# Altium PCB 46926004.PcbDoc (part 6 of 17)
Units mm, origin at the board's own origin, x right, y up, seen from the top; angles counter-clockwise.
Board outline 250 x 200 mm, 6 copper layers (Top Layer, INT1_GND, INT2_SIG, INT3_SIG, INT4_GND, Bottom Layer), stack 1.71 mm thick; 1450 components, 1293 nets, 5656 pads, 2307 vias.
Unrouted connection lines stored in the file: 2.
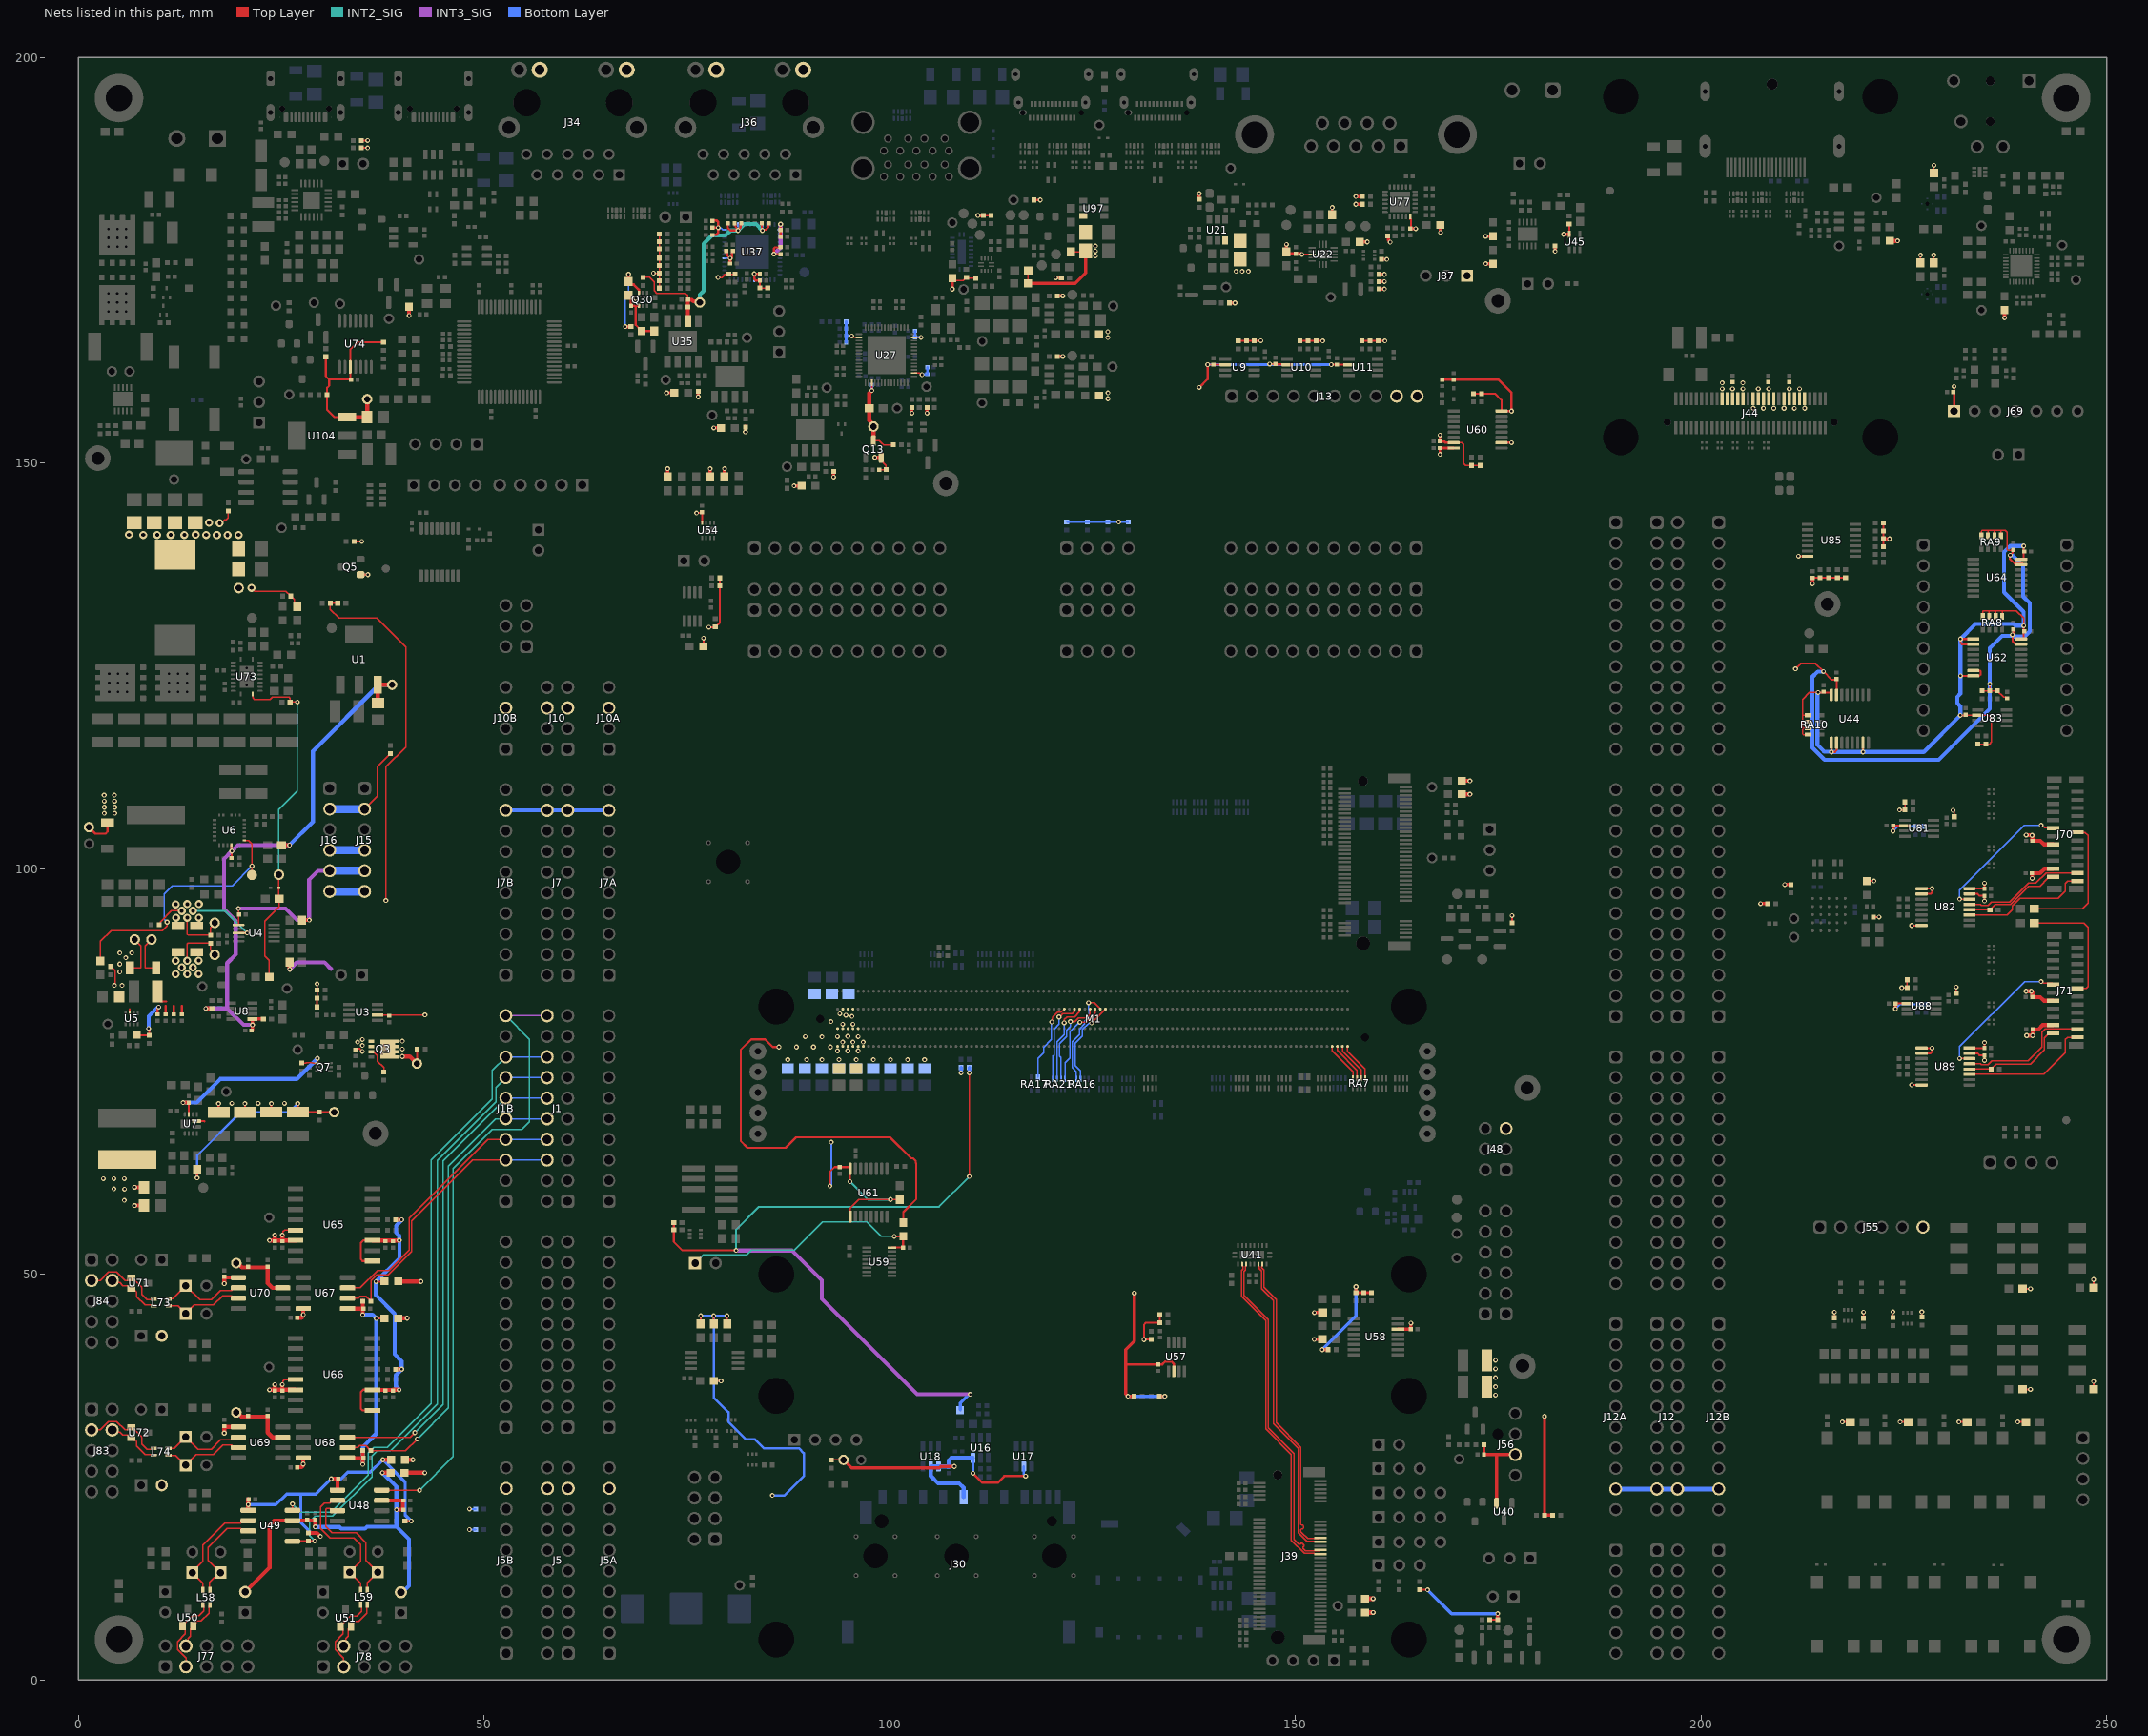
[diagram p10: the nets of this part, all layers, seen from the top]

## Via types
v1: diameter 0.6, hole 0.3, Top Layer to Bottom Layer, tented both sides, 2171 vias
v2: diameter 0.6, hole 0.3, Top Layer to Bottom Layer, 48 vias
v3: diameter 1, hole 0.5, Top Layer to Bottom Layer, tented both sides, 37 vias
v4: diameter 0.5, hole 0.2, Top Layer to Bottom Layer, tented both sides, 34 vias
v5: diameter 0.6, hole 0.3, Top Layer to Bottom Layer, tented bottom, 17 vias

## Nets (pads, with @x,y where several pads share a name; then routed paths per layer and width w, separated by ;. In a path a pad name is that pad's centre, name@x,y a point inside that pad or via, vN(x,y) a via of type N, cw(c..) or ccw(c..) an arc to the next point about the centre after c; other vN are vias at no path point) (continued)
1V8: C8.2 C65.2 C66.2 C69.2 C96.2 C98.1 C207.2 C228.2 C234.2 C239.2 C241.2 C242.2 C245.2 C304.1 C311.2 C312.2 C317.2 C318.2 C342.2 C351.2 C354.2 C359.2 C393.2 C394.2 J5.17 J5.18 J5A.9 J5B.9 J7.17 J7.18 J7A.9 J7B.9 J10.5 J10.6 J10A.3 J10B.3 J12.17 J12.18 J12A.9 J12B.9 J15.6 J16.6 J44.43 J44.45 J44.47 J44.49 J44.51 J48.5 J55.6 J69.1 J87.1 L21.1 L57.1 L60.1 L62.2 L63.1 L72.1 L78.1 Q5.1 Q30.4 R39.2 R61.1 R66.1 R75.1 R76.1 R108.1 R118.1 R140.1 R141.1 R180.2 R182.1 R193.1 R198.1 R221.1 R222.1 R223.1 R230.1 R231.1 R232.1 R233.1 R234.1 R238.1 R240.1 R242.1 R244.1 R246.1 R255.1 R258.1 R260.1 R262.1 R266.1 R268.1 R269.1 R271.1 R284.2 R300.1 R302.1 R340.1 R343.2 R383.2 R384.2 R385.2 R391.2 R392.1 R408.2 R409.2 R410.2 R411.2 R412.2 R413.1 R414.1 R418.2 R426.1 R427.1 R432.2 R442.1 R443.1 R455.1 R456.1 R468.2 R469.2 R470.2 R471.2 R472.2 R475.2 R476.2 R477.1 R478.1 RA8.5 RA8.6 RA8.7 RA8.8 RA10.5 RA10.6 RA10.7 RA10.8 U3.2 U9.2 U10.2 U11.2 U44.1 U44.2 U44.7 U44.16 U45.5 U54.8 U57.2 U60.2 U60.8 U60.16 U61.1 U61.16 U62.1 U62.2 U62.7 U62.8 U62.16 U64.16 U77.18 U81.2 U82.1 U82.2 U82.8 U82.16 U83.2 U85.14 U88.2 U89.1 U89.2 U89.8 U89.16 X19.1 | length 396.5
  Top Layer w0.15: R39.2@6.375,87.775 7.637,87.775 7.725,87.863 7.725,90.489 X19.1@6.941,91.273 ; U3.2@36.87,81.975 v1(42.721,81.975) ; U61.1@95.114,56.814 95.114,58.181 96.172,59.239 100.093,59.239 v1(100.102,59.23) 100.111,59.239 R284.2@101.239,59.239 ; RA10.8@213.175,116.525 212.578,116.525 212.5,116.603 212.5,117.325 ; RA10.7@213.175,117.325 212.5,117.325 ; RA10.6@213.175,118.125 212.5,118.125 ; RA10.5@213.175,118.925 212.5,118.925 ; v1(214.425,121.725) 213.354,121.725 212.5,120.871 212.5,118.925 ; R302.1@227.05,174.675 v1(227.05,175.625) ; R340.1@228.675,174.675 v1(228.675,175.625) ; R300.1@228.7,185.75 v1(228.7,186.7) ; v1(231.175,159.45) 231.175,158.8 231.2,158.775 C342.2@231.2,158.525 ; C351.2@232.625,118.9 U83.2@234.105,118.9 235.425,118.9 235.8,118.525 235.8,115.6 235.55,115.35 R442.1@235.1,115.35 R443.1@234.1,115.35 ; RA8.8@234.712,131.125 234.712,131.722 234.79,131.8 235.512,131.8 ; RA8.7@235.512,131.125 235.512,131.8 ; RA8.6@236.312,131.125 236.312,131.8 ; RA8.5@237.112,131.125 237.112,131.8 ; v1(239.75,129.95) 239.75,130.875 238.825,131.8 237.112,131.8 ; 212.5,117.325 212.5,118.125 ; 212.5,118.125 212.5,118.925 ; 235.512,131.8 236.312,131.8 ; 236.312,131.8 237.112,131.8
  Top Layer w0.25: Q5.1@34.764,136.25 v1(35.689,136.25) ; 68.684,169.389 68.684,167.042 C98.1@69.302,166.425 ; v1@76.2,143.843 C228.2@76.865,143.843 ; R232.1@76.7,43.9 v1(76.7,44.9) ; U54.8@76.87,142.663 C228.2@76.87,143.838 ; L21.1@77.05,127.425 v1(77.05,128.425) ; L63.1@78.295,36.865 v1(79.2,36.865) ; R233.1@78.3,43.9 v1(78.3,44.9) ; R234.1@79.95,43.9 v1(79.95,44.9) ; v1(92.613,60.881) 92.613,62.626 93.2,63.214 C239.2@93.814,63.214 94.991,63.214 U61.16@95.114,63.091 ; v1(95.114,61.429) U61.16@95.114,63.014 U61.16@95.114,63.091 ; U61.16@95.114,63.314 U61.16@95.114,63.091 ; R391.2@117.795,182.432 v1(118.55,182.432) ; v1(139.19,162.133) C65.2@139.885,162.133 ; C65.2@140,162.13 140.002,162.128 141.357,162.128 U9.2@141.36,162.125 ; v1(146.829,162.2) C66.2@147.515,162.2 147.552,162.163 148.942,162.163 U10.2@148.98,162.125 ; v1(154.43,162.133) C69.2@155.125,162.133 ; C69.2@155.24,162.13 155.242,162.128 156.597,162.128 U11.2@156.6,162.125 ; C304.1@164.15,178.9 164.249,178.999 164.249,179.951 164.156,180.044 164.156,180.179 U77.18@164.15,180.185 U77.18@164.15,180.375 ; v1@164.817,178.898 v1(164.82,178.895) ; R193.1@165.33,11.125 v1(166.3,11.125) ; C354.2@167.823,151.85 C354.2@167.826,151.852 ; U60.16@169.498,151.852 U60.16@169.5,151.855 ; R456.1@171.95,158.55 R455.1@172.95,158.55 174.601,158.55 175.4,157.751 U60.8@175.4,156.405 ; R182.1@173.937,7.423 R418.2@174.928,7.423 ; R198.1@176.693,93.35 v1(176.693,94.235) ; v1(181.995,176.111) v1@181.997,176.114 ; R432.2@181.997,176.779 R432.2@182,176.781 ; R343.2@183.725,179.475 183.737,179.462 183.737,178.213 U45.5@183.748,178.202 ; v1(212.004,138.525) U85.14@213.121,138.525 ; C359.2@213.725,135.86 R476.2@214.672,135.86 R469.2@215.75,135.86 R468.2@216.8,135.86 R408.2@217.8,135.86 ; v1(214.425,121.725) U44.16@216.05,121.725 ; U44.1@216.05,115.225 v1(216.05,114.4) 216.511,114.4 216.7,114.589 U44.2@216.7,115.225 ; v1(217.401,31.811) R246.1@218.409,31.811 ; U44.7@219.95,115.225 219.956,115.219 219.956,114.406 v1(219.961,114.4) ; L62.2@220.41,98.485 v1(221.31,98.485) ; R230.1@221.25,94.05 v1(221.925,94.05) ; R475.2@222.484,139.681 R472.2@222.484,142.603 ; C311.2@223.666,105.315 U81.2@225.12,105.315 ; C317.2@223.951,83.39 U88.2@225.404,83.39 ; v1(224.526,31.811) R244.1@225.534,31.811 ; v1@225.964,73.348 U89.8@227.179,73.348 ; v1@225.965,93 U82.8@227.18,93 ; U89.2@227.179,77.248 228.308,77.248 228.454,77.395 v1(228.454,77.898) U89.1@227.179,77.898 ; U82.2@227.18,96.9 228.308,96.9 228.455,97.046 v1(228.455,97.55) U82.1@227.18,97.55 ; J69.1@231.17,156.4 231.2,156.43 C342.2@231.2,158.525 ; v1(231.776,31.811) R242.1@232.784,31.811 ; v1(231.95,118.9) C351.2@232.625,118.9 ; v1@231.997,123.775 U62.8@233.55,123.775 234.304,123.775 234.45,123.921 234.45,124.314 234.339,124.425 U62.7@233.25,124.425 ; U89.16@233.079,77.898 C318.2@234.929,77.898 v1(234.929,78.562) ; U82.16@233.08,97.55 C312.2@234.93,97.55 v1(234.93,98.214) ; U62.2@233.25,127.675 232.121,127.675 231.975,127.821 v1(231.975,128.325) U62.1@233.25,128.325 ; v1(239.026,31.811) R240.1@240.034,31.811 ; R255.1@239.625,35.825 v1(240.6,35.825) ; R258.1@239.625,48.225 v1(240.6,48.225) ; U62.16@239.75,128.325 v1(239.75,129.95) ; U64.16@239.75,138.15 v1(239.75,139.775) ; R260.1@248.375,35.825 v1(248.375,36.8) ; R262.1@248.375,48.375 v1(248.375,49.35)
  Top Layer w0.3: R180.2@67.8,170.7 67.8,170.577 R180.2@67.814,170.563 ; v1(68.67,170.263) 68.124,170.263 C96.2@68.124,169.389 68.684,169.389 Q30.4@69.076,169.389 ; C98.1@69.302,166.425 69.441,166.285 C98.1@69.441,166.26 R61.1@70.95,166.26 ; v1(85.525,22.761) v1@85.539,22.775 ; 129.1,38.977 129.177,38.9 C234.2@133.063,38.9 133.602,38.9 133.952,39.25 134.729,39.25 135.002,38.977 U57.2@135.002,38.065 ; v1(138.15,159.325) 139.19,160.365 v1(139.19,162.133) ; v1(167.826,151.077) 167.826,151.852 U60.16@169.498,151.852 ; C393.2@168.083,160.285 174.995,160.285 176.625,158.655 v1(176.625,156.405) U60.8@175.4,156.405 ; U60.2@175.4,152.505 v1(176.625,152.505)
  Top Layer w0.4: R221.1@72.62,148.31 v1(72.62,149.31) ; R222.1@77.87,148.31 v1(77.87,149.31) ; R223.1@79.62,148.31 v1(79.62,149.31) ; v1(120.47,172.843) R392.1@121.15,172.843 ; R141.1@120.644,170.613 v1(121.324,170.613) ; R140.1@120.654,163.14 v1(121.334,163.14) ; R477.1@130.118,34.978 v1(129.351,34.978) 129.1,35.229 129.1,38.977 129.1,40.742 130.143,41.784 130.143,41.809 130.145,41.811 130.145,47.681 v1(130.147,47.683) ; R478.1@133.241,34.978 v1(133.9,34.978) ; R108.1@138.145,182.536 138.147,182.538 138.147,183.203 v1(138.15,183.206) ; v1(153.298,40.712) R266.1@154.024,40.712 ; v1(157.45,182.85) R384.2@158.25,182.85 ; v1(157.45,181.9) R383.2@158.25,181.9 ; v1(157.461,48.468) R271.1@157.461,47.743 R269.1@158.411,47.743 R268.1@159.359,47.743 ; R118.1@160.299,171.463 160.964,171.463 v1(160.966,171.46) ; R385.2@161.348,177.998 161.352,177.998 161.45,177.9 161.45,177.505 161.67,177.285 v1(161.67,177.231) ; C304.1@164.249,178.898 v1@164.817,178.898 ; v1(173.45,174.575) L78.1@174.375,174.575 ; R418.2@174.928,7.423 v1(174.928,8.187) ; v1@181.997,176.114 R432.2@181.997,176.779 ; v1(183.08,178.205) 183.083,178.202 U45.5@183.748,178.202 ; v1(207.325,95.7) 207.437,95.7 R231.1@208.185,95.7 ; v1(210.312,98.04) R238.1@211.06,98.04 ; v1@213.725,135.115 C359.2@213.725,135.86 ; R470.2@222.484,140.656 v1@223.228,140.656 ; v1(223.661,104.645) 223.664,104.648 C311.2@223.664,105.313 ; v1(223.946,82.72) 223.948,82.723 C317.2@223.948,83.388
  Top Layer w0.5: L72.1@39.456,44.525 39.516,44.585 40.525,44.585 v1(40.535,44.595) ; L57.1@40.225,27.15 v1(41.225,27.15) ; v1(237.4,167.9) L60.1@237.4,168.85
  INT2_SIG w0.25: v1(95.114,61.429) 97.313,59.23 v1(100.102,59.23)
  Bottom Layer w0.15: R413.1@121.8,142.725 R414.1@124.34,142.725 R426.1@126.88,142.725 R427.1@129.42,142.725
  Bottom Layer w0.25: v1(48.2,18.54) R75.1@48.955,18.54 ; v1(48.2,21.08) R76.1@48.955,21.08 ; v1(76.7,44.9) v1(78.3,44.9) v1(79.95,44.9) ; v1(92.613,60.881) 92.792,61.061 v1(92.792,66.29) ; v1(223.661,104.645) 224.241,105.225 R409.2@226.416,105.225 R410.2@227.409,105.225 ; v1(223.946,82.72) 224.525,83.3 R411.2@226.7,83.3 R412.2@227.694,83.3
  Bottom Layer w0.3: v1(78.3,44.9) 78.3,34.825 80.125,33 80.125,31.82 82.283,29.662 83.391,29.662 84.475,28.578 87.377,28.578 87.386,28.57 88.785,28.57 89.4,27.955 89.4,25.141 87.02,22.761 v1(85.525,22.761)
  Bottom Layer w0.4: v1(108.8,74.84) R66.1@108.8,75.5 ; v1(129.351,34.978) v1(133.9,34.978) ; v1(139.19,162.133) v1(154.43,162.133) ; v1(153.298,40.712) 157.461,44.875 v1(157.461,48.468) ; v1(166.3,11.125) 169.239,8.187 v1(174.928,8.187)
  Bottom Layer w0.5: J7B.9@52.68,107.2 J7.18@57.76,107.2 J7.17@60.3,107.2 J7A.9@65.38,107.2 ; v1(214.425,121.725) 214.345,121.645 214.345,115.241 215.167,114.419 216.031,114.419 v1(216.05,114.4) v1(219.961,114.4) 227.45,114.4 v1(231.95,118.9) 231.963,118.913 231.963,120.022 231.575,120.41 231.575,121.192 231.963,121.58 231.963,128.313 v1(231.975,128.325) 233.817,130.167 238.547,130.167 238.763,129.95 v1(239.75,129.95) 239.75,131.675 237.35,134.075 237.35,139.025 238.1,139.775 v1(239.75,139.775)
  Bottom Layer w0.6: J12A.9@189.47,23.54 J12.17@194.55,23.54 J12.18@197.09,23.54 J12B.9@202.17,23.54
  Bottom Layer w1: J16.6@30.977,97.204 J15.6@35.277,97.204
  other v1: 225.959,73.353 5.103,87.277 5.103,88.25 5.825,89.025 5.103,89.608 6.575,89.608 225.96,93.005 231.986,123.786 213.722,135.112 223.231,140.653 128.22,142.725 76.195,143.848 210.227,156.75 211.507,156.74 212.767,156.75 210.862,159.15 212.132,159.15
1V8_CAN_A: C209.2 C210.2 L57.2 R43.1 R50.1 U48.5 U49.5 | length 41.5
  Top Layer w0.15: U48.5@31.919,23.405 U48.5@31.925,23.41 ; R50.1@40.25,19.6 v1(41.025,19.6)
  Top Layer w0.5: U49.5@20.924,20.916 20.925,20.917 v1(20.925,21.625) 20.925,22.304 C210.2@20.924,22.305 ; R43.1@28.351,18.133 29.392,18.133 v1(29.825,17.7) ; v1(31.15,24.8) 31.925,24.8 U48.5@31.925,23.41 ; v1(37.525,27.15) L57.2@38.525,27.15
  Bottom Layer w0.4: v1(20.925,21.625) 24.35,21.625 25.66,22.935 27.414,22.935 ; v1(29.825,17.7) 29.771,17.7 29.338,18.133 28.651,18.133 27.414,19.371 27.414,22.935 ; v1(41.025,19.6) 40.275,20.35 40.275,24.4 v1(37.525,27.15) 35.975,25.6 33.2,25.6 32.4,24.8 v1(31.15,24.8) 29.285,22.935 27.414,22.935
1V8_CAN_B: C251.2 C252.2 L72.2 R67.1 R68.1 U67.1 U68.1 | length 28.7
  Top Layer w0.15: U68.1@33.169,27.38 U68.1@33.189,27.36 ; L72.2@37.69,44.55 L72.2@37.704,44.565
  Top Layer w0.25: v1(36.725,44.55) L72.2@37.69,44.55
  Top Layer w0.5: U67.1@33.173,45.795 33.194,45.775 C251.2@35.05,45.775 ; U68.1@33.189,27.36 C252.2@35.045,27.36 ; v1(35.045,26.58) C252.2@35.045,27.36 ; R68.1@35.045,28.285 C252.2@35.045,27.36 ; v1(35.05,45.025) C251.2@35.05,45.775 ; R67.1@35.05,46.7 C251.2@35.05,45.775
  Bottom Layer w0.5: v1(35.045,26.58) 35.045,28.695 36.725,30.375 v1(36.725,44.55) 36.25,45.025 v1(35.05,45.025)
1V8_ETH2: C99.1 C130.1 C141.2 C142.2 C143.2 C157.2 C161.2 C165.2 C168.2 C171.1 C174.1 C178.1 Q30.3 R62.2 R150.2 R152.2 R154.2 R156.1 R158.2 R162.2 R164.2 R168.2 R173.2 R174.2 R175.2 R180.1 R450.2 U37.13 U37.19 U37.30 U37.41 U37.48 | length 42.2
  Top Layer w0.15: v1(70.876,173.412) R156.1@71.595,173.412 ; R150.2@71.595,171.562 R156.1@71.595,173.412 ; R162.2@71.595,178.237 R164.2@71.595,177.312 R158.2@71.595,176.387 R156.1@71.595,173.412 ; v1(78.825,172.875) 79.293,172.875 79.693,173.275 R154.2@80.15,173.275 80.155,173.28 R152.2@80.92,173.28
  Top Layer w0.2: R175.2@83.988,171.575 84.949,171.575 R174.2@84.958,171.583 ; R175.2@83.988,171.575 C174.1@83.988,172.525
  Top Layer w0.25: C157.2@79.85,176.025 79.975,175.9 79.975,175.571 80.296,175.25 v1(80.325,175.25) 80.325,174.75 80.374,174.701 C171.1@80.385,174.701 ; v1@80.55,175.375 80.55,175.925 C161.2@80.65,176.025 ; C178.1@86.55,175.75 v1(85.725,175.75) 85.725,176.454 85.871,176.6 C168.2@86.55,176.6
  Top Layer w0.3: R180.1@67.814,172.279 68.093,172 68.441,172 69.076,171.366 Q30.3@69.076,170.969 ; C130.1@78.125,178.16 78.65,178.16 78.875,178.385 v1(78.875,179.01) ; C142.2@78.125,179.01 v1(78.875,179.01) ; C143.2@78.125,179.91 78.65,179.91 78.7,179.86 78.875,179.685 v1(78.875,179.01) ; C174.1@83.988,172.525 83.466,172.525 83.3,172.691 v1(83.3,173.35) C165.2@83.988,173.35 ; C99.1@86.55,177.925 v1(86.55,179.44)
  Top Layer w0.4: v1(67.418,166.81) R173.2@68.098,166.81 ; R180.1@67.8,172.4 v1(67.8,173.288) ; C171.1@80.325,174.585 v1(80.325,175.25)
  INT3_SIG w0.5: v1(85.725,175.75) 86.55,176.575 v1(86.55,179.44)
  Bottom Layer w0.15: v1(67.418,166.81) 67.418,170.32 67.798,170.699 67.798,173.151 v1@67.814,173.167
  Bottom Layer w0.2: v1(78.875,179.01) 78.952,178.933 79.276,178.933 79.459,178.75 U37.48@79.65,178.75 ; U37.41@79.65,175.25 v1(80.325,175.25) ; U37.30@83.3,172.6 v1(83.3,173.35) ; v1(85.725,175.75) U37.19@86.45,175.75 ; U37.13@86.45,178.75 86.482,178.75 86.5,178.768 86.5,179.39 v1(86.55,179.44)
2V5_ETH2: C153.2 C163.2 C166.2 C169.2 C172.1 C175.1 R121.2 R169.2 U35.6 U37.3 U37.9 X56.1 | length 35.4
  Top Layer w0.15: R121.2@69.576,172.89 70.395,172.89 70.95,172.335 70.95,171.282 71.295,170.937 74.819,170.937 75.098,170.658 75.098,170.173 C153.2@75.125,170.146
  Top Layer w0.25: C166.2@80.05,179.575 80.05,178.975 80.35,178.675 v1(81.3,178.675) ; C163.2@80.875,179.475 80.91,179.44 80.975,179.44 80.975,179.125 81.233,178.867 81.233,178.742 v1(81.3,178.675) ; C172.1@81.7,179.475 81.649,179.475 81.614,179.44 81.614,178.996 81.3,178.683 v1(81.3,178.675) ; C175.1@84.225,179.475 84.225,178.845 84.3,178.77 v1(84.3,178.675) 84.363,178.738 84.691,178.738 85.039,179.086 85.039,179.44 C169.2@85.074,179.475
  Top Layer w0.5: U35.6@75.125,167.504 R169.2@75.125,169.254 C153.2@75.125,170.146 75.135,170.136 75.6,170.136 75.785,169.951 76.435,169.951 X56.1@76.588,169.798
  INT2_SIG w0.5: X56.1@76.588,169.798 76.601,169.811 76.601,170.765 77.047,171.211 77.047,177.017 78.08,178.05 79.75,178.05 80.375,178.675 v1(81.3,178.675) ; v1@81.319,178.694 82.075,179.45 83.525,179.45 v1(84.3,178.675)
  Bottom Layer w0.2: v1(81.3,178.675) U37.3@81.3,179.4 ; v1(84.3,178.675) U37.9@84.3,179.4
3V3: C12.2 C14.2 C94.2 C129.2 C204.2 C243.2 C244.2 C246.2 C313.2 C315.2 C319.2 C321.2 C352.2 C353.2 J13.9 J13.10 J15.4 J15.5 J16.4 J16.5 J34.11 J34.13 J36.11 J36.13 J44.31 J44.33 J44.35 J44.37 J44.39 J70.15 J71.15 L15.1 L20.1 L31.2 L41.2 L42.2 L46.1 L47.1 L48.1 L49.1 L75.1 L79.1 L80.1 L91.1 Q13.2 R12.1 R13.1 R14.1 R17.1 R18.1 R27.2 R51.2 R52.2 R69.1 R70.1 R71.1 R72.1 R73.1 R74.1 R77.1 R78.1 R79.1 R100.1 R102.1 R103.1 R104.2 R106.1 R113.1 R116.1 R117.1 R135.2 R363.1 R364.1 R365.1 R371.1 R372.1 R373.1 R375.2 R376.2 R377.2 R394.2 R402.1 R403.1 R444.1 R445.1 R446.1 R453.1 R454.1 R457.1 R458.1 R459.1 RA9.5 RA9.6 RA9.7 RA9.8 U4.6 U5.7 U22.3 U44.15 U60.15 U62.15 U64.15 U82.15 U89.15 X24.1 | length 301.8
  Top Layer w0.15: R27.2@4,87.95 4.525,87.425 4.525,85.7 v1(4.45,85.625) ; U4.6@19.725,93.075 19.725,94.35 v1(19.725,95.089) ; C129.2@98.711,149.198 R135.2@99.558,149.198 99.558,149.723 98.946,150.335 Q13.2@98.946,150.674 ; L91.1@107.71,172.811 108.023,172.497 109.056,172.497 R377.2@109.456,172.897 109.561,172.793 R394.2@110.627,172.793 ; v1(109.8,62.064) v1(109.8,74.84) ; R376.2@111.554,180.51 111.556,180.512 R375.2@112.495,180.512 ; v1(150.804,175.715) U22.3@152.046,175.715 ; U60.15@169.5,152.505 170.526,152.505 170.75,152.281 170.75,149.955 171,149.705 R453.1@171.726,149.705 R454.1@172.782,149.705 ; v1(224.45,107.245) 224.452,107.243 R365.1@225.117,107.243 ; v1(224.734,85.32) 224.737,85.317 R373.1@225.402,85.317 ; R365.1@225.12,107.24 R364.1@225.12,108.23 ; R373.1@225.404,85.315 R373.1@225.404,85.335 R372.1@225.404,86.305 ; RA9.8@234.55,141.025 234.55,141.622 234.628,141.7 235.35,141.7 ; R445.1@234.653,121.925 R446.1@235.578,121.925 ; RA9.7@235.35,141.025 235.35,141.7 ; v1@235.578,122.747 R446.1@235.578,121.925 ; RA9.6@236.15,141.025 236.15,141.7 ; RA9.5@236.95,141.025 236.95,141.7 ; C352.2@237.7,120.9 237.7,120.95 237.525,121.125 237.3,121.125 R444.1@236.5,121.925 R446.1@235.578,121.925 ; C246.2@238.5,139.225 237.85,139.225 237.7,139.375 237.7,141.5 237.5,141.7 236.95,141.7 ; 235.35,141.7 236.15,141.7 ; 236.15,141.7 236.95,141.7
  Top Layer w0.2: R12.1@29.413,82.965 29.413,84.013 R14.1@29.425,84.025 R13.1@29.425,85.025 v1(29.425,85.796) ; R71.1@142.95,165.059 145.716,165.059 v1(145.738,165.082) ; R72.1@150.57,165.059 v1(153.362,165.059) ; R78.1@158.19,165.059 v1(161.025,165.059) ; v1(231.03,107.2) 231.2,107.03 R363.1@231.2,106.4 ; R371.1@231.44,84.645 v1(231.44,85.412)
  Top Layer w0.25: X24.1@1.3,105.116 2.091,104.325 3.337,104.325 3.582,104.569 R51.2@3.582,105.675 ; U5.7@6.325,82.197 6.325,82.665 ; R52.2@34.004,140.34 v1(34.929,140.34) ; R402.1@34.85,188.85 v1(35.65,188.85) ; R403.1@34.85,189.75 v1(35.65,189.75) ; R457.1@73.384,56.393 R458.1@73.384,55.475 73.384,54.009 74.443,52.95 v1(81.068,52.95) ; v1(77.705,129.775) 78.501,129.775 79.075,130.349 79.075,130.383 79.076,130.384 79.076,131.212 79.075,131.213 R102.1@79.075,134.885 R103.1@79.075,135.835 ; v1(211.635,124.64) 212.274,125.279 214.107,125.279 v1(215.082,124.304) 216.107,123.279 216.707,123.279 216.704,123.275 216.704,121.729 U44.15@216.7,121.725 ; U89.15@233.079,77.248 233.085,77.243 234.08,77.243 234.315,77.008 234.895,77.008 C319.2@234.926,76.977 C319.2@234.956,76.946 ; U82.15@233.08,96.9 233.085,96.895 234.08,96.895 234.315,96.659 234.895,96.659 C313.2@234.957,96.598 ; C319.2@234.906,76.896 234.929,76.873 v1(234.929,76.378) ; C313.2@234.906,96.548 234.93,96.524 v1(234.93,96.03) ; v1@238.057,138.607 v1(238.1,138.65) ; v1(238.359,128.83) v1@238.486,128.83 ; C243.2@238.433,129.467 238.486,129.414 238.486,128.709 238.375,128.598 238.375,128.052 238.652,127.775 239.65,127.775 U62.15@239.75,127.675 ; C246.2@238.5,139.225 238.41,139.225 238.375,139.19 238.375,138.926 v1(238.1,138.65) ; U64.15@239.75,137.5 239.65,137.6 238.652,137.6 238.05,138.202 238.05,138.6 v1(238.1,138.65)
  Top Layer w0.3: L46.1@158.606,8.322 L46.1@158.611,8.327 ; L47.1@158.606,10.022 L47.1@158.609,10.024 ; v1(167.823,153.45) C353.2@167.823,152.675 167.851,152.648 168.352,152.648 168.495,152.505 U60.15@169.5,152.505
  Top Layer w0.4: v1(72.502,158.66) L41.2@73.42,158.66 ; v1(78.307,154.323) L42.2@79.225,154.323 ; v1(88.208,147.186) L31.2@89.126,147.186 ; v1(98.171,150.699) 98.183,150.686 98.934,150.686 Q13.2@98.946,150.674 ; v1(107.71,171.439) L91.1@107.71,172.791 ; v1(110.874,180.51) R376.2@111.554,180.51 ; R104.2@141.872,169.74 142.537,169.74 v1(142.54,169.737) ; R106.1@148.871,176.015 149.071,175.815 C94.2@150.071,175.815 150.11,175.777 150.689,175.777 150.75,175.715 v1(150.804,175.715) ; R106.1@148.899,176.015 148.899,176.942 v1(148.901,176.945) ; R117.1@160.299,172.363 160.964,172.363 v1(160.966,172.36) ; R116.1@160.299,173.263 160.964,173.263 v1(160.966,173.26) ; R113.1@160.599,175.113 161.264,175.113 v1(161.266,175.11) ; v1(167.875,178.425) L79.1@167.875,179.35 ; v1(173.448,177.95) L80.1@174.373,177.95
  Top Layer w0.5: v1(26.042,87.6) R18.1@26.042,88.475 ; R17.1@27.55,93.675 v1(28.45,93.675) ; v1(40.755,168.199) L15.1@40.755,169.247 ; L48.1@170.528,109.179 v1(171.503,109.179) ; L49.1@170.528,110.829 v1(171.503,110.829) ; L75.1@223.25,177.392 v1(224.225,177.392) ; v1(240.053,84.906) v1(240.703,84.906) 240.703,84.879 240.819,84.763 240.819,84.206 C321.2@240.829,84.196 240.85,84.175 241.813,84.175 242.258,83.73 J71.15@243.4,83.73 ; v1(240.07,104.145) 240.084,104.131 240.775,104.131 v1(240.789,104.118) ; v1@240.804,104.141 240.829,104.116 240.829,103.456 C315.2@240.85,103.435 241.813,103.435 242.258,102.99 J70.15@243.4,102.99
  Top Layer w0.6: L47.1@158.609,10.024 v1(159.579,10.024) ; L46.1@158.611,8.327 v1(159.581,8.327)
  INT3_SIG w0.5: v1(19.725,95.089) 25.521,95.089 26.935,93.675 v1(28.45,93.675) 28.45,98.662 29.532,99.744 J16.5@30.977,99.744 ; v1(26.042,87.6) 26.91,88.468 30.332,88.468 31.15,87.65 ; v1(81.068,52.95) 87.924,52.95 91.62,49.254 91.62,46.983 103.388,35.216 v1(109.91,35.216)
  INT2_SIG w0.25: v1(81.068,52.95) 81.068,55.527 83.871,58.33 106.066,58.33 v1(109.8,62.064)
  Bottom Layer w0.4: L20.1@108.664,33.28 108.711,33.327 108.711,34.146 109.743,35.177 109.871,35.177 v1(109.91,35.216) ; v1(109.8,74.84) R459.1@109.8,75.5
  Bottom Layer w0.5: v1(215.082,124.304) 214.379,124.304 213.695,123.62 213.695,114.955 215.225,113.425 229.275,113.425 235.575,119.725 v1(235.575,122.75) 235.575,127.192 237.09,128.706 v1@238.359,128.706 ; v1(238.1,138.65) 238.375,138.65 239.7,137.325 239.7,133.55 240.5,132.75 240.5,129.25 239.86,128.61 238.582,128.61 238.486,128.706 v1@238.359,128.706 ; v1(238.359,128.83) v1@238.359,128.706
  Bottom Layer w1: J16.5@30.977,99.744 J15.5@35.277,99.744 ; J16.4@30.977,102.284 J15.4@35.277,102.284
  other v1: 5.375,85.625 3.2,106.825 4.49,106.825 3.2,107.573 4.476,107.573 3.186,108.32 4.461,108.32 3.171,109.068 4.447,109.068 206.417,156.75 207.687,156.75 208.957,156.75 207.052,159.15 208.322,159.15
3V3_PG: R38.2 U6.1 X17.1 | length 32.7
  Top Layer w0.15: R38.2@2.725,88.625 2.725,91.057 4.046,92.379 10.349,92.379 10.925,92.955 v1(10.925,93.425) ; U6.1@20.445,103.487 20.979,103.487 21.391,103.076 v1(21.391,100.338) X17.1@21.391,99.225
  Bottom Layer w0.15: v1(10.925,93.425) 10.574,93.776 10.574,96.876 11.598,97.9 18.953,97.9 v1(21.391,100.338)
3V3_SD: C91.2 C280.2 C282.2 J30.4 R99.2 U16.6 U17.5 U18.4 U18.5 X32.1 | length 39.9
  Top Layer w0.15: R99.2@92.775,27.131 X32.1@94.3,27.131
  Top Layer w0.3: v1(110.25,25.481) 111.431,24.3 113.304,24.3 114.128,25.124 v1(116.742,25.124)
  Top Layer w0.4: X32.1@94.3,27.131 95.298,26.133 95.936,26.133 96.764,26.133 106.1,26.133 106.287,26.32 v1(107.96,26.32)
  Bottom Layer w0.3: v1(110.25,25.481) U16.6@110.25,27.37 ; U17.5@116.525,26.32 116.525,25.342 v1(116.742,25.124)
  Bottom Layer w0.4: C91.2@107.3,26.32 v1(107.96,26.32)
  Bottom Layer w0.5: J30.4@109.1,22.525 109.1,23.7 108.55,24.25 105.95,24.25 105.05,25.15 U18.5@105.05,26.32 U18.4@106,26.32 C91.2@107.3,26.32 107.3,27.1 107.57,27.37 C280.2@108.066,27.37 C282.2@108.924,27.37 U16.6@110.25,27.37
3V3_UHUB: C105.2 C106.2 C111.2 C113.2 C115.2 C118.2 C121.1 C124.1 Q13.3 R65.1 R122.1 R125.2 R128.2 R131.1 U27.16 U27.31 U27.44 U27.55 X47.1 | length 21
  Top Layer w0.2: v1(95.32,165.674) 95.428,165.674 95.608,165.495 96.191,165.495 U27.16@96.193,165.493 ; v1(97.794,158.951) U27.31@97.794,159.891 ; Q13.3@97.996,152.774 98.698,152.774 99.224,152.249 R122.1@100.445,152.249 ; U27.44@102.995,161.093 103.669,161.093 103.864,160.897 v1(103.97,160.897) ; U27.55@102.995,165.493 v1(103.862,165.493)
  Top Layer w0.4: v1(102.737,156.157) R125.2@102.737,156.837 ; v1(104.596,156.157) R128.2@104.596,156.837
  Top Layer w0.5: v1(97.794,158.951) 97.794,158.937 97.466,158.608 R131.1@97.466,156.764 97.466,155.257 97.996,154.727 X47.1@97.996,154.511 Q13.3@97.996,153.254
  Bottom Layer w0.2: v1(97.794,158.951) v1@97.795,158.952 ; C111.2@97.796,159.64 C111.2@97.796,159.64
  Bottom Layer w0.3: C113.2@94.622,164.86 C118.2@94.622,165.694 ; R65.1@94.622,167.443 C105.2@94.622,166.56 C118.2@94.622,165.694 ; v1(95.32,165.674) 95.31,165.684 94.632,165.684 C118.2@94.622,165.694 ; v1@97.795,158.952 C111.2@97.796,159.64 ; C121.1@103.1,166.3 C115.2@103.1,165.5 103.104,165.496 103.859,165.496 v1(103.862,165.493) ; v1(103.97,160.897) 103.998,160.925 104.596,160.925 C124.1@104.624,160.953 C106.2@104.624,161.8
5V: C10.2 C13.2 C15.2 C17.2 C180.2 C181.2 C183.2 C185.2 C187.2 C283.2 L4.1 L9.2 Q3.S Q7.4 R19.2 R21.2 R22.1 R23.1 R53.1 R309.1 R318.1 R431.2 U7.9 X10.1 X90.1 | length 46.1
  Top Layer w0.15: v3@13.425,88.675 13.425,90.737 13.513,90.825 R21.2@16.3,90.825 16.3,90.005 16.8,89.505 X10.1@16.8,89.391 X10.1@16.8,89.608 ; v3(17.41,142.61) 17.64,142.61 18.017,142.987 18.233,142.987 18.465,143.219 R431.2@18.465,144.105 ; v3(21.34,134.625) 21.744,134.221 25.579,134.221 R318.1@26.195,133.605 26.632,133.168 26.632,132.685 R309.1@26.992,132.325 ; R53.1@27.55,76.05 28.054,76.05 28.079,76.075 28.865,76.075 28.89,76.05 Q7.4@29.46,76.05 29.458,76.052 v1(29.458,76.62) ; Q3.S@36.125,77.45 36.26,77.315 36.488,77.315 36.85,76.953 36.85,76.275 37.65,75.475 R19.2@37.65,74.92
  Top Layer w0.25: C17.2@13.6,71.075 13.609,71.066 U7.9@13.609,69.717 ; C10.2@34.125,77.8 34.675,77.8 v1(35,77.475)
  Top Layer w0.5: v1@6.916,58.46 v1(6.936,58.479) 8.099,58.479 C15.2@8.103,58.475 ; v1@6.939,60.725 6.943,60.729 8.099,60.729 C13.2@8.103,60.725 ; v1(12.901,71.175) C17.2@13.5,71.175 ; X10.1@16.8,89.391 X10.1@16.8,89.608
  Bottom Layer w0.5: v1(12.901,71.175) 14.584,71.175 17.489,74.08 26.917,74.08 v1(29.458,76.62)
  other v1: 5.65,59.125 5.675,60.5 4.375,60.525 6.936,60.729 3.075,61.8 4.375,61.8 5.65,61.8 35,78.225 34.425,78.625 35,78.95
  other v3: 11.999,87.025 13.425,87.025 14.835,87.035 12.725,87.85 14.125,87.85 11.999,88.675 13.425,88.675 14.825,88.676 17.07,141.125 18.365,141.135 6.225,141.16 7.99,141.145 9.715,141.155 11.37,141.15 13.065,141.155 14.475,141.16 15.76,141.15 19.735,141.145 16.1,142.635
5V_CAN_A: C211.2 C212.2 C213.2 C214.2 J80.2 J82.2 L56.2 U48.3 U49.3 | length 48.2
  Top Layer w0.5: J80.2@20.551,10.853 23.55,13.852 23.55,19.075 24.122,19.647 29.197,19.647 C214.2@29.2,19.65 ; v1(29.198,18.873) C214.2@29.198,19.648 ; U48.3@37.38,22.135 37.39,22.125 39.975,22.125 39.975,21 v1(39.2,21) ; v1(37.475,25.55) L56.2@38.475,25.55
  Bottom Layer w0.5: v1(29.198,18.873) 32.164,18.873 32.387,18.65 35.325,18.65 35.575,18.9 39.2,18.9 ; v1(37.475,25.55) 39.2,23.825 v1(39.2,21) 39.2,18.9 ; J82.2@39.985,10.815 39.985,10.857 40.735,11.608 40.735,17.365 39.2,18.9
5V_CAN_B: C247.2 C248.2 C249.2 C250.2 L71.2 R289.2 R290.2 U65.1 U65.3 U66.1 U66.3 | length 43.6
  Top Layer w0.25: U66.1@36.248,33.23 35.021,33.23 34.82,33.43 34.82,35.495 35.1,35.775 36.242,35.775 U66.3@36.248,35.77 U66.3@36.253,35.765 ; U65.1@36.253,51.645 35.025,51.645 34.825,51.845 34.825,53.91 35.105,54.19 36.247,54.19 U65.3@36.253,54.185 U65.3@36.257,54.18 ; v1(36.675,49.1) L71.2@37.684,49.1
  Top Layer w0.5: U66.3@36.253,35.765 37.845,35.765 38.787,35.765 38.787,35.768 39.533,35.768 v1(39.535,35.77) ; U65.3@36.257,54.18 37.85,54.18 38.791,54.18 38.791,54.182 39.537,54.182 v1(39.54,54.185) ; R290.2@39.096,38.31 v1(39.845,38.31) ; R289.2@39.1,56.725 v1(39.85,56.725)
  Bottom Layer w0.5: v1(36.675,49.1) 36.675,47.425 38.976,45.124 38.976,40.149 39.845,39.28 v1(39.845,38.31) 39.145,37.61 39.145,36.188 v1@39.535,35.798 ; v1@36.694,49.119 39.559,51.984 v1@39.559,54.166 ; v1(39.54,54.185) 39.54,54.745 39.15,55.135 39.15,55.998 39.85,56.698 v1(39.85,56.725)
5V_ENABLE: D43.1 R64.2 R303.2 R307.1 U73.1 X86.1 | length 42.5
  Top Layer w0.15: U73.1@21.492,121.525 21.492,121.075 21.692,120.875 23.617,120.875 23.892,121.15 25.942,121.15 26.092,121 R307.1@26.092,120.525 26.116,120.549 v1(26.992,120.549) ; R64.2@23.525,86.65 23.525,88.7 22.988,89.237 22.988,93.538 24.725,95.275 R303.2@24.725,96.325 24.707,96.343 D43.1@24.707,97.675 X86.1@24.707,99.271
  INT2_SIG w0.15: X86.1@24.707,99.271 24.707,107.269 26.992,109.554 v1(26.992,120.549)
5V_ISO1: C254.2 C255.2 C257.2 C261.2 C262.2 C356.2 J90.2 U65.13 U65.14 U67.8 U70.3 U70.5 X82.1 | length 18.8
  Top Layer w0.15: v1(25.13,54.83) 25.216,54.916 25.216,55.221 25.225,55.229 25.225,55.265 25.415,55.455 U65.13@26.753,55.455
  Top Layer w0.5: v1(17.985,48.855) 17.985,49.585 18.005,49.605 U70.5@19.72,49.605 ; X82.1@19.457,51.392 19.608,51.392 20.15,50.85 23.33,50.85 23.33,48.91 23.91,48.33 25.175,48.33 U70.3@25.181,48.335 ; v1@23.56,54.185 C257.2@24.2,54.185 ; v1@24.2,54.825 C257.2@24.2,54.185 ; C254.2@25.135,54.185 v1@25.135,54.825 ; U65.14@26.753,54.185 C257.2@24.2,54.185 ; C356.2@27.055,44.64 27.505,44.64 27.712,44.847 U67.8@27.712,45.795
  other v1: 27.712,45.033 23.555,54.18 24.195,54.83
5V_ISO2: C253.2 C256.2 C258.2 C259.2 C260.2 C357.2 J86.2 U66.13 U66.14 U68.8 U69.3 U69.5 X83.1 | length 18.8
  Top Layer w0.15: v1(25.125,36.415) 25.211,36.501 25.211,36.806 25.22,36.815 25.22,36.85 25.41,37.04 U66.13@26.748,37.04
  Top Layer w0.5: v1(17.98,30.44) 17.98,31.17 18,31.19 U69.5@19.715,31.19 ; X83.1@19.457,32.975 19.58,32.975 20.119,32.435 23.325,32.435 23.325,30.495 23.905,29.915 25.171,29.915 U69.3@25.176,29.92 ; v1@23.556,35.77 C258.2@24.196,35.77 ; v1@24.196,36.41 C258.2@24.196,35.77 ; C256.2@25.13,35.77 v1@25.13,36.41 ; U66.14@26.748,35.77 C258.2@24.196,35.77 ; C357.2@27.048,26.223 27.498,26.223 27.705,26.43 U68.8@27.705,27.378
  other v1: 27.705,26.616 23.551,35.765 24.191,36.415
5V_Mux: C238.2 J58.1 L66.2 U59.16 | length 31.3
  Top Layer w0.25: U59.16@100.263,53.3 C238.2@101.65,53.3 101.65,54.65 L66.2@101.675,54.675 v1(100.56,54.675)
  INT2_SIG w0.15: J58.1@76.01,51.388 77.047,52.425 82.366,52.425 82.944,53.003 88.263,53.003 91.71,56.45 97.175,56.45 98.95,54.675 v1(100.56,54.675)
5V_PD: C285.2 C287.2 R314.2 R324.2 R333.2 U74.3 U104.3 X110.1 | length 25.1
  Top Layer w0.25: R314.2@30.5,163.1 30.5,160.7 30.9,160.3 ; U104.3@33.4,155.675 31.55,155.675 30.625,156.6 R333.2@30.625,158.45 30.625,159.25 30.9,159.525 30.9,160.3 ; R324.2@37.6,164.9 36.695,164.9 34.425,164.9 33.5,163.975 U74.3@33.5,161.85 33.5,160.3 30.9,160.3
  Top Layer w0.5: U104.3@33.4,155.675 C285.2@35.6,155.675 X110.1@35.6,157.875
5V_S: C28.2 C206.2 C236.2 C316.2 C322.2 C325.2 C343.2 C344.2 J15.2 J16.2 J44.19 J44.21 J44.23 J44.25 J44.27 J70.21 J71.21 L26.1 L32.1 L33.1 L56.1 L71.1 L92.1 Q3.D R24.2 R40.2 R109.2 R123.2 R159.2 R160.2 R248.1 R249.1 R250.1 R253.1 R254.1 R264.1 R265.1 R279.2 R280.2 R281.2 R282.2 R386.2 R390.2 U21.6 U58.6 U97.6 X11.1 | length 73.3
  Top Layer w0.15: J15.2@35.277,107.364 36.82,108.907 36.82,112.551 R40.2@38.444,114.175 ; L92.1@117.049,172.149 117.049,173.709 R386.2@117.075,173.735 ; R390.2@122.321,176.021 124.021,176.021 C344.2@124.146,176.146 ; R282.2@216.425,44.65 v1(216.425,45.35) ; R281.2@220.025,44.6 v1(220.025,45.35) ; R280.2@223.625,44.7 v1(223.625,45.375) ; v1(227.2,45.375) 227.2,44.775 R279.2@227.225,44.75
  Top Layer w0.25: X11.1@41.725,75.975 R24.2@41.725,77.775 ; R248.1@132.236,41.983 131.355,41.983 v1(131.325,41.953) 131.325,43.791 131.583,44.05 R250.1@133.302,44.05 R249.1@133.302,45.05
  Top Layer w0.3: R109.2@154.546,180.59 v1(154.546,181.51)
  Top Layer w0.4: v1(76.395,158.168) R159.2@76.395,158.848 ; v1(82.2,153.831) R160.2@82.2,154.511 ; v1(93.085,148.271) R123.2@93.085,148.95 ; L92.1@117.075,172.25 117.176,172.149 122.876,172.149 124.146,173.419 C344.2@124.146,176.146 ; v1(152.323,41.983) R254.1@153.324,41.983 ; v1(152.338,45.283) R253.1@153.339,45.283 ; L26.1@157.946,177.265 v1(158.846,177.265) ; U58.6@162.637,43.253 162.64,43.251 164.234,43.251 C236.2@164.237,43.248 v1(164.237,43.996) ; v1(180.694,32.488) R264.1@180.694,20.306 R265.1@181.689,20.306
  Top Layer w0.5: L71.1@39.4,49.125 39.402,49.123 42.218,49.123 v1(42.22,49.12) ; v1(39.925,76.85) 40.85,76.85 X11.1@41.725,75.975 ; L56.1@40.175,25.55 v1(42.7,25.55) ; v1(240.125,79.438) v1(240.863,79.438) C322.2@240.863,80.175 241.556,80.175 242.101,80.72 243.39,80.72 J71.21@243.4,80.73 ; v1(240.804,98.811) 240.804,99.431 C316.2@240.794,99.441 241.766,99.441 242.315,99.99 J70.21@243.4,99.99
  Bottom Layer w1: J16.2@30.977,107.364 J15.2@35.277,107.364
  other v1: 39.925,77.775 39.925,78.75 126.886,157.925 126.886,158.65 202.607,159.15 203.877,159.15 205.147,159.15 202.603,159.889 205.143,159.889 126.88,165.463 126.88,166.188 142.672,173.63 143.442,173.63 144.205,173.63 125.35,175.532 125.35,176.135 125.35,176.758
5V_STB: C4.2 C22.2 C48.2 R32.1 R55.2 R58.2 U1.3 U6.21 U8.1 X1.1 | length 70.8
  Top Layer w0.25: C22.2@18.866,101.425 18.88,101.44 18.88,102.155 v1(18.895,102.169) ; v1@18.868,102.169 18.868,102.911 U6.21@18.87,102.913
  Top Layer w0.4: C48.2@21.45,80.05 v1(21.45,80.75) 21.45,81.46 U8.1@21.465,81.475 R55.2@22.8,81.475
  Top Layer w0.5: v1(15.711,82.775) R58.2@16.45,82.775 ; R32.1@25.041,102.907 v1(26.016,102.907) ; C4.2@36.925,120.4 36.9,120.425 U1.3@36.9,122.675 X1.1@38.663,122.675
  INT3_SIG w0.5: v1(15.711,82.775) 18.325,82.775 ; v1(21.45,80.75) 20.35,80.75 18.325,82.775 ; v1(26.016,102.907) 19.659,102.907 18.922,102.169 v1(18.895,102.169) 17.941,101.216 17.941,95.021 19.4,93.562 19.4,89.441 18.325,88.366 18.325,82.775
  Bottom Layer w0.5: v1(26.016,102.907) 28.9,105.791 28.9,114.493 37.082,122.675 X1.1@38.663,122.675
5V_T: C51.2 C52.2 C53.2 C54.2 C55.2 C56.2 C57.2 C58.2 C59.2 C60.2 C61.2 C62.2 C63.2 C64.2 L66.1 M1.B97 M1.B98 M1.B99 M1.C96 M1.C97 M1.C98 M1.C99 M1.C100 M1.D95 M1.D96 M1.D97 M1.D98 M1.D99 M1.D100 R22.2 R23.2 R25.2 R26.2 R239.1 R358.1 U4.8 X12.1 | length 113.2
  Top Layer w0.15: R26.2@9.965,93.075 10.1,93.21 10.1,93.445 11.48,94.825 12.7,94.825 v3(12.725,94.8) ; v3(13.425,93.975) 13.425,91.913 13.513,91.825 R25.2@16.3,91.825 16.3,92.714 16.802,93.216 X12.1@16.802,93.325 ; U4.8@19.68,92.075 U4.8@19.725,92.075 ; R358.1@31.961,132.722 R239.1@31.036,132.722 31.036,131.989 32.134,130.891 36.759,130.891 40.35,127.3 40.35,115.004 37.9,112.553 v1(37.9,96.07)
  Top Layer w0.25: U4.8@19.725,92.075 v1(20.805,92.075) ; v1(86.339,78.03) 85.573,78.03 84.64,78.963 82.938,78.963 81.63,77.655 81.63,66.439 82.47,65.599 87.159,65.599 88.46,66.9 100.036,66.9 102.636,64.3 102.863,64.3 103.2,63.963 103.2,63.736 103.271,63.665 103.271,59.271 101.675,57.675 L66.1@101.675,56.375
  INT2_SIG w0.25: v3(14.125,94.8) 18.08,94.8 v1(20.805,92.075)
  other v1: 87.425,76.465 89.725,76.465 91.639,76.465 95.865,76.465 97.989,76.465 100.089,76.465 102.189,76.465 104.289,76.465 93.742,76.468 93.561,77.561 94.831,77.561 96.101,77.561 88.502,78.03 90.602,78.03 92.702,78.03 94.196,78.639 95.466,78.639 96.736,78.639 91.65,79.275 89.575,79.3 93.55,79.3 96.1,79.3 94.825,79.325 94.196,80.839 95.466,80.839 92.756,81.159 95.35,81.8 94.6,81.95 93.839,82.119
  other v3: 12.025,93.974 14.851,93.975 12.015,95.615 13.425,95.625 14.851,95.625
12V: C18.2 C19.2 C40.2 C43.2 C237.2 C331.2 C332.2 J56.2 R48.1 R274.2 R430.2 U7.6 U40.2 X21.1 | length 39.7
  Top Layer w0.25: U7.6@14.559,68.892 14.572,68.88 15.522,68.88 15.534,68.867 ; v1(14.627,61.875) R48.1@14.627,62.95 ; C331.2@17.28,69.975 v1(17.28,71.05) ; C332.2@20.53,69.975 v1(20.53,71.05) ; C43.2@23.786,69.981 v1(23.786,71.056) ; v1(27.032,71.056) C40.2@27.032,69.981 27.039,69.988 R430.2@29.705,69.988 X21.1@31.532,69.988
  Top Layer w0.4: R274.2@173.237,29 C237.2@173.237,27.775 174.775,27.775 ; U40.2@174.775,21.8 174.775,27.775 ; J56.2@177.1,27.775 174.775,27.775
  Bottom Layer w0.25: v1(14.627,61.875) 14.627,64.627 20,70 25.976,70 v1(27.032,71.056)
  other v1: 174.65,35.125 174.65,36.15 174.65,37.275 174.65,38.35 174.65,39.4 18.9,71.075 22.15,71.075 25.407,71.081
A0_N: J39.35 U41.4 | length 41
  Top Layer w0.15: U41.4@143.923,51.25 143.923,51.07 143.823,50.97 143.823,50.513 143.675,50.365 143.675,47.42 146.663,44.432 146.663,31.066 149.8,27.929 149.8,17.349 150.149,17 150.431,16.718 150.572,16.718 150.689,16.836 150.831,16.836 151.043,16.624 151.043,16.482 150.926,16.365 150.926,16.224 151.224,15.925 151.44,15.925 152.312,15.925 152.337,15.95 153.025,15.95 J39.35@153.1,16.025
A0_P: J39.37 U41.3 | length 41
  Top Layer w0.15: U41.3@143.423,51.25 143.423,51.07 143.523,50.97 143.523,50.638 143.375,50.489 143.375,47.296 146.363,44.307 146.363,30.942 149.5,27.805 149.5,17.225 151.1,15.625 152.312,15.625 152.337,15.6 153.025,15.6 J39.37@153.1,15.525
A1_N: J39.29 U41.8 | length 38.3
  Top Layer w0.15: U41.8@145.923,51.25 145.878,51.205 145.878,50.968 145.848,50.937 145.848,50.813 146.103,50.557 146.103,48.39 147.626,46.867 147.626,31.724 150.65,28.7 150.65,19.673 150.65,19.178 150.74,19.088 150.923,19.088 151.013,18.998 151.013,18.728 150.923,18.638 150.74,18.638 150.65,18.548 150.65,18.299 150.837,18.113 151.524,17.425 152.312,17.425 152.337,17.45 153.025,17.45 J39.29@153.1,17.525
A1_P: J39.31 U41.7 | length 38.3
  Top Layer w0.15: U41.7@145.423,51.25 145.423,51.07 145.548,50.945 145.548,50.689 145.803,50.433 145.803,48.266 147.326,46.743 147.326,31.599 150.35,28.576 150.35,18.175 151.4,17.125 152.312,17.125 152.337,17.1 153.025,17.1 J39.31@153.1,17.025
ADC_1: M1.D01 RA7.1 | length 4.8
  Top Layer w0.15: M1.D01@156.432,78.1 156.432,77.518 158.6,75.35 RA7.1@158.6,74.15
ADC_2: M1.D02 RA7.2 | length 4.9
  Top Layer w0.15: M1.D02@155.797,78.1 155.797,77.503 158.1,75.2 RA7.2@158.1,74.15
ADC_3: M1.D03 RA7.3 | length 5
  Top Layer w0.15: M1.D03@155.162,78.1 155.162,77.588 157.6,75.15 RA7.3@157.6,74.15
ADC_4: M1.D04 RA7.4 | length 5
  Top Layer w0.15: M1.D04@154.527,78.1 154.527,77.548 157.1,74.975 RA7.4@157.1,74.15
BUCK_1V8: C16.1 C21.2 C24.2 C25.2 C26.2 L5.2 R29.2 R39.1 X18.1 | length 15.2
  Top Layer w0.15: C16.1@7.174,79.535 C16.1@7.259,79.45 ; v1(8.65,80.31) v1@8.725,80.235 ; X18.1@9.005,91.275 8.225,90.495 8.225,87.863 8.313,87.775 R39.1@9.575,87.775
  Top Layer w0.25: C16.1@7.259,79.45 R29.2@8.725,79.45 v1@8.725,80.235 ; C16.1@7.325,79.622 C16.1@7.328,79.625 ; C26.2@9.755,82.153 9.755,82.688 9.833,82.766 9.833,82.873 v1(9.9,82.94) ; L5.2@10.086,83.628 10.825,83.628 ; C25.2@10.755,82.153 10.755,83.078 ; C24.2@11.755,82.153 11.755,83.103 ; C21.2@12.755,82.153 12.755,83.103
  Bottom Layer w0.5: v1(8.65,80.31) 8.675,80.31 8.675,81.817 9.778,82.92 9.881,82.92 v1(9.9,82.94)
CAM_1_CON_IC_DETECT: J70.23 R366.2 U82.12 | length 12
  Top Layer w0.15: U82.12@233.08,94.95 235.568,94.95 R366.2@235.598,94.92 236.278,95.599 238.132,95.599 240.363,97.831 241.751,97.831 242.731,98.811 243.221,98.811 J70.23@243.4,98.99
CAM_1_CON_MCLK: J70.12 R359.1 | length 16.7
  Top Layer w0.15: R359.1@241.075,95.05 247,95.05 247.7,95.75 247.7,104.112 247.322,104.49 J70.12@246.4,104.49
CAM_1_CON_PWRCTRL: J70.24 U82.11 | length 15.9
  Top Layer w0.15: U82.11@233.08,94.3 237.729,94.3 238.358,94.928 238.358,95.401 239.307,96.35 244.028,96.35 244.9,97.222 244.9,98.2 245.19,98.49 J70.24@246.4,98.49
CAM_1_CON_PWRDWN: J70.22 U82.13 | length 15
  Top Layer w0.15: U82.13@233.08,95.6 234.431,95.6 234.541,95.49 235.395,95.49 235.804,95.899 238.008,95.899 240.338,98.23 241.251,98.23 242.511,99.49 J70.22@246.4,99.49
CAM_1_CON_RST: J70.11 U82.14 | length 17.3
  Top Layer w0.15: v1@231.87,96.253 U82.14@233.077,96.253 ; v1(241.913,105.353) 242.035,105.353 242.356,105.032 J70.11@243.358,105.032
  Bottom Layer w0.15: v1(231.868,96.25) 231.868,97.36 239.86,105.353 v1(241.913,105.353)
CAM_2_CON_IC_DETECT: J71.23 R374.2 U89.12 | length 13
  Top Layer w0.15: U89.12@233.079,75.298 R374.2@235.732,75.298 236.367,75.933 240.619,75.933 242.33,77.644 242.33,79.15 242.731,79.551 243.221,79.551 J71.23@243.4,79.73
CAM_2_CON_MCLK: J71.12 R367.1 | length 15.5
  Top Layer w0.15: R367.1@241.075,93.275 247.185,93.275 247.7,92.76 247.7,85.47 247.46,85.23 J71.12@246.4,85.23
CAM_2_CON_PWRCTRL: J71.24 U89.11 | length 16.2
  Top Layer w0.15: U89.11@233.079,74.648 242.251,74.648 244.9,77.297 244.9,78.94 245.19,79.23 J71.24@246.4,79.23
CAM_2_CON_PWRDWN: J71.22 U89.13 | length 16.2
  Top Layer w0.15: U89.13@233.079,75.948 234.431,75.948 234.541,75.838 235.395,75.838 235.855,76.298 240.286,76.298 242.03,78.042 242.03,79.82 242.44,80.23 J71.22@246.4,80.23
CAM_2_CON_RST: J71.11 U89.14 | length 17.6
  Top Layer w0.15: v1@231.87,76.601 U89.14@233.077,76.601 ; v1(241.905,86.099) 242.027,86.099 242.211,85.915 243.215,85.915 J71.11@243.358,85.772
  Bottom Layer w0.15: v1(231.867,76.598) 231.867,78.097 239.869,86.099 v1(241.905,86.099)
CAN1_N: J74.1 L73.2 U70.6 | length 10.7
  Top Layer w0.15: L73.2@11.125,46.967 11.173,47.014 11.644,47.014 J74.1@13.23,48.6 14.963,46.867 16.373,46.867 17.531,48.025 18.842,48.025 19.152,48.335 U70.6@19.787,48.335
CAN1_P: J68.1 L73.3 U70.7 | length 10.1
  Top Layer w0.15: L73.3@11.125,46.117 12.263,46.117 J68.1@13.23,45.15 14.297,46.217 16.642,46.217 17.8,47.375 18.842,47.375 19.152,47.065 U70.7@19.787,47.065
CAN2_N: J75.1 L74.2 U69.6 | length 10.5
  Top Layer w0.15: L74.2@11.125,28.55 11.806,28.55 13.223,29.966 14.739,28.45 16.373,28.45 17.531,29.608 18.842,29.608 19.152,29.918 U69.6@19.787,29.918
CAN2_P: J73.1 L74.3 U69.7 | length 10.3
  Top Layer w0.15: L74.3@11.125,27.7 12.006,27.7 13.223,26.483 14.54,27.8 16.642,27.8 17.8,28.958 18.842,28.958 19.152,28.648 U69.7@19.787,28.648
CAN3_N: J29.1 L58.2 U49.6 | length 13.4
  Top Layer w0.15: L58.2@15.336,11.138 15.336,11.952 13.995,13.293 15.346,14.643 15.346,16.615 18.064,19.333 19.976,19.333 20.286,19.643 U49.6@20.921,19.643
CAN3_P: J49.1 L58.3 U49.7 | length 12.4
  Top Layer w0.15: L58.3@16.186,11.138 16.186,12.018 17.461,13.293 15.996,14.759 15.996,16.346 18.333,18.683 19.976,18.683 20.286,18.373 U49.7@20.921,18.373
CAN4_N: J45.1 L59.2 U48.6 | length 17.5
  Top Layer w0.15: U48.6@31.919,22.135 31.284,22.135 30.974,21.825 30.333,21.825 29.827,21.319 29.827,18.673 31.01,17.49 33.965,17.49 34.784,16.671 34.784,14.63 J45.1@33.434,13.28 34.775,11.939 L59.2@34.775,11.125
CAN4_P: J64.1 L59.3 U48.7 | length 16.5
  Top Layer w0.15: U48.7@31.919,20.865 31.284,20.865 30.974,21.175 30.602,21.175 30.477,21.05 30.477,18.942 31.279,18.14 34.235,18.14 35.434,16.941 35.434,14.746 J64.1@36.9,13.28 35.625,12.005 L59.3@35.625,11.125
CAN_1_N: J84.3 L73.1 U71.1 | length 10.3
  Top Layer w0.15: J84.3@1.623,49.24 2.678,49.24 3.728,50.29 4.703,50.29 5.751,49.242 5.987,49.242 6.2,49.242 U71.1@6.525,49.567 6.65,49.567 7.825,48.392 7.825,47.524 8.482,46.867 9.175,46.867 L73.1@9.275,46.967
CAN_1_P: J84.4 L73.4 U71.2 | length 6.8
  Top Layer w0.15: J84.4@4.163,49.24 4.42,48.983 5.091,48.983 5.482,48.592 6.2,48.592 U71.2@6.525,48.267 6.85,47.942 7.087,47.942 7.175,47.854 7.175,47.254 8.213,46.217 9.175,46.217 L73.4@9.275,46.117
CAN_1_RX: M1.B49 RA16.1 | length 12.3
  Top Layer w0.15: v1(124.496,83.472) 125.18,83.472 M1.B49@125.946,82.706
  Bottom Layer w0.15: RA16.1@122.996,74.072 122.996,74.977 122.5,75.474 122.5,78.659 123.371,79.53 123.371,80.226 124.053,80.908 124.053,81.205 124.585,81.736 124.585,82.597 124.496,82.685 v1(124.496,83.472)
CAN_1_RX_JMP: J1.8 J1B.4 U67.3 | length 34.5
  Top Layer w0.15: U67.3@33.173,48.335 34.743,48.335 36.893,50.485 38.25,50.485 40.775,53.01 40.775,56.915 50.5,66.64 J1B.4@52.68,66.64
  Bottom Layer w0.15: J1B.4@52.68,66.64 J1.8@57.76,66.64
CAN_1_TX: M1.B48 RA16.2 | length 10.6
  Top Layer w0.15: v1(124.861,80.977) v1(124.861,80.977) 126.579,82.694 M1.B48@126.593,82.694
  Bottom Layer w0.15: RA16.2@123.496,74.072 123.496,75.096 122.871,75.721 122.871,78.523 123.746,79.398 123.746,80.177 124.483,80.913 124.796,80.913 v1(124.861,80.977)
CAN_1_TX_JMP: J1.6 J1B.3 R67.2 U67.2 | length 35.8
  Top Layer w0.15: U67.2@33.173,47.065 34.465,47.065 34.7,47.3 35.45,47.3 R67.2@36.05,46.7 36.05,49.217 36.783,49.95 38.185,49.95 41.075,52.84 41.075,56.575 48.6,64.1 J1B.3@52.68,64.1
  Bottom Layer w0.15: J1B.3@52.68,64.1 J1.6@57.76,64.1
CAN_2_N: J83.3 L74.1 U72.1 | length 10.3
  Top Layer w0.15: J83.3@1.623,30.823 2.678,30.823 3.728,31.873 4.703,31.873 5.751,30.825 5.987,30.825 6.2,30.825 U72.1@6.525,31.15 6.65,31.15 7.825,29.975 7.825,29.107 8.482,28.45 9.175,28.45 L74.1@9.275,28.55
CAN_2_P: J83.4 L74.4 U72.2 | length 6.8
  Top Layer w0.15: J83.4@4.163,30.823 4.42,30.566 5.091,30.566 5.481,30.175 6.2,30.175 U72.2@6.525,29.85 6.85,29.525 7.087,29.525 7.175,29.437 7.175,28.837 8.213,27.8 9.175,27.8 L74.4@9.275,27.7
CAN_2_RX: M1.B51 RA21.3 | length 11.2
  Top Layer w0.15: v1(122.268,81.162) 122.272,81.166 122.793,81.166 123.252,81.625 124.277,81.625 124.682,82.03 M1.B51@124.682,82.7
  Bottom Layer w0.15: RA21.3@121.11,74.07 121.11,76.737 120.91,76.937 120.91,78.439 121.808,79.337 121.808,80.095 122.265,80.552 122.265,81.158 v1(122.268,81.162)
CAN_2_RX_JMP: J1.12 J1B.6 U68.3 | length 59.5
  Top Layer w0.15: U68.3@33.169,29.92 40.87,29.92 41.454,30.504 v1(41.463,30.496)
  INT2_SIG w0.15: v1(41.463,30.496) 41.454,30.504 41.825,30.875 41.842,30.875 44.95,33.983 44.95,63.99 J1B.6@52.68,71.72
  Bottom Layer w0.15: J1B.6@52.68,71.72 J1.12@57.76,71.72
CAN_2_TX: M1.B50 RA21.4 | length 10.7
  Top Layer w0.15: v1(123.432,81.062) 124.203,81.062 125.317,82.176 125.317,82.687 M1.B50@125.323,82.694
  Bottom Layer w0.15: RA21.4@121.61,74.07 121.61,76.112 122.2,76.702 122.2,79.903 123.359,81.062 v1(123.432,81.062)
CAN_2_TX_JMP: J1.10 J1B.5 R68.2 U68.2 | length 59.3
  Top Layer w0.15: U68.2@33.169,28.65 34.46,28.65 34.695,28.885 35.445,28.885 R68.2@36.045,28.285 ; R68.2@36.05,28.275 40.325,28.275 v1(41.75,29.7)
  INT2_SIG w0.15: v1(41.75,29.7) 45.571,33.521 45.571,63.336 51.415,69.18 J1B.5@52.68,69.18
  Bottom Layer w0.15: J1B.5@52.68,69.18 J1.10@57.76,69.18
CAN_3_N: J77.3 L58.1 U50.1 | length 10.2
  Top Layer w0.15: J77.3@13.256,1.643 13.256,2.698 12.206,3.748 12.206,4.715 13.186,5.695 13.186,6.075 13.186,6.288 12.861,6.613 12.861,6.738 14.036,7.913 14.854,7.913 15.436,8.495 15.436,9.188 L58.1@15.336,9.288
CAN_3_P: J77.4 L58.4 U50.2 | length 6.6
  Top Layer w0.15: J77.4@13.256,4.183 13.517,4.444 13.517,5.107 13.836,5.426 13.836,6.288 14.161,6.613 14.486,6.938 14.486,7.175 14.574,7.263 15.124,7.263 16.086,8.226 16.086,9.188 L58.4@16.186,9.288
CAN_3_RX: M1.B54 RA21.1 | length 10.5
  Top Layer w0.15: v1(120.86,81.722) 120.953,81.722 121.35,82.119 122.483,82.119 122.777,82.414 M1.B54@122.777,82.7
  Bottom Layer w0.15: RA21.1@120.11,74.07 120.11,76.922 120.243,77.055 120.243,80.218 120.86,80.835 v1(120.86,81.722)
CAN_3_RX_JMP: J1.16 J1B.8 U49.4 | length 77
  Top Layer w0.15: U49.4@26.382,20.913 v1(26.382,21.688)
  INT2_SIG w0.15: v1(26.382,21.688) 27.364,20.706 31.131,20.706 33.895,23.47 35.7,25.275 35.7,27.95 36.4,28.65 38.05,28.65 43.5,34.1 43.5,64.125 51,71.625 51,75.12 J1B.8@52.68,76.8
  Bottom Layer w0.15: J1B.8@52.68,76.8 J1.16@57.76,76.8
CAN_3_TX: M1.B53 RA21.2 | length 10.3
  Top Layer w0.15: v1(121.508,81.009) 121.529,81.03 121.529,81.43 121.829,81.73 122.769,81.73 123.412,82.373 M1.B53@123.412,82.7
  Bottom Layer w0.15: RA21.2@120.61,74.07 120.61,78.656 121.508,79.554 v1(121.508,81.009)
CAN_3_TX_JMP: J1.14 J1B.7 R43.2 U49.1 | length 77.5
  Top Layer w0.15: U49.1@26.382,17.103 26.412,17.133 R43.2@28.351,17.133 v1(29.126,17.133)
  INT2_SIG w0.15: v1(29.126,17.133) 28.475,17.784 28.475,19.485 29.185,20.195 31.345,20.195 36.2,25.05 36.2,27.61 36.865,28.275 38.5,28.275 44.223,33.998 44.223,64.039 51.449,71.265 51.449,73.029 J1B.7@52.68,74.26
  Bottom Layer w0.15: J1B.7@52.68,74.26 J1.14@57.76,74.26
CAN_4_N: J78.3 L59.1 U51.1 | length 10.2
  Top Layer w0.15: J78.3@32.695,1.63 32.695,2.685 31.645,3.735 31.645,4.702 32.625,5.682 32.625,6.062 32.625,6.275 U51.1@32.3,6.6 32.3,6.725 33.475,7.9 34.293,7.9 34.875,8.482 34.875,9.175 L59.1@34.775,9.275
CAN_4_P: J78.4 L59.4 U51.2 | length 6.6
  Top Layer w0.15: J78.4@32.695,4.17 32.956,4.431 32.956,5.094 33.275,5.413 33.275,6.275 U51.2@33.6,6.6 33.925,6.925 33.925,7.162 34.013,7.25 34.562,7.25 35.525,8.213 35.525,9.175 L59.4@35.625,9.275
CAN_4_RX: M1.B56 RA17.2 | length 10
  Top Layer w0.15: v1(119.96,81.108) 120.04,81.189 120.04,81.633 120.115,81.708 120.115,81.72 120.693,82.297 121.104,82.297 121.501,82.694 M1.B56@121.513,82.694
  Bottom Layer w0.15: RA17.2@118.276,74.27 118.276,76.631 118.967,77.323 118.967,77.972 119.943,78.948 119.943,80.882 119.96,80.899 v1(119.96,81.108)
CAN_4_RX_JMP: J1.20 J1B.10 U48.4 | length 77.2
  Top Layer w0.15: U48.4@37.38,23.405 37.4,23.385 v1(42.045,23.385)
  INT3_SIG w0.15: J1B.10@52.68,81.88 J1.20@57.76,81.88
  INT2_SIG w0.15: v1(42.045,23.385) 46.2,27.54 46.2,63.057 51.01,67.867 54.662,67.867 55.6,68.805 55.6,78.96 J1B.10@52.68,81.88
